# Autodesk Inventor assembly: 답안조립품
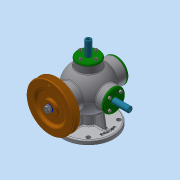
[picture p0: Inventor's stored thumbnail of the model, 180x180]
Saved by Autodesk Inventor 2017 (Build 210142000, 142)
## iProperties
Part Number: 답안조립품
Material: 일반
Document SubType Name: Assembly
Designer: MRC
Mass: 3415.99 g
Surface Area: 2410.88 cm^2
Volume: 904.616 cm^3
Density: 3.77618 g/cm^3
Author: MRC
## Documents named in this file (17)
- C:\Users\MRC\Desktop\시험\600911V1004\답안조립품.iam
- C:\Users\MRC\Desktop\시험\600911V1004\본체.ipt
- C:\Users\MRC\Desktop\시험\600911V1004\V-벨트풀리.ipt
- C:\Users\MRC\Desktop\시험\600911V1004\너트 M8x1.ipt
- C:\Users\MRC\Desktop\시험\600911V1004\뒤커버.ipt
- C:\Users\MRC\Desktop\시험\600911V1004\베어링 6202.ipt
- C:\Users\MRC\Desktop\시험\600911V1004\본체커버.ipt
- C:\Users\MRC\Desktop\시험\600911V1004\볼트 M4.ipt
- C:\Users\MRC\Desktop\시험\600911V1004\스프링1.ipt
- C:\Users\MRC\Desktop\시험\600911V1004\스프링2.ipt
- C:\Users\MRC\Desktop\시험\600911V1004\슬라이드 커버.ipt
- C:\Users\MRC\Desktop\시험\600911V1004\슬라이드.ipt
- C:\Users\MRC\Desktop\시험\600911V1004\앞커버.ipt
- C:\Users\MRC\Desktop\시험\600911V1004\오일 실.ipt
- C:\Users\MRC\Desktop\시험\600911V1004\와셔 8x17.ipt
- C:\Users\MRC\Desktop\시험\600911V1004\축.ipt
- C:\Users\MRC\Desktop\시험\600911V1004\키 4x4.ipt
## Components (1 placed, 1 different names)
1. V-벨트풀리:1
